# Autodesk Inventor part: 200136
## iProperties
Created: 2007-10
Part Number: 200136
Document SubType Name: Modeling
Designer: TH
Density: 7.85 g/cm^3
Mass: 540.598 g
Surface Area: 646.996 cm^2
Volume: 68.8659 cm^3
Material: Steel
Description: TOP BACK PLATE
Component Category: Lower Component
Author: TH
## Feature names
1. Extrusion1
2. Extrusion2
3. Mirror1
4. Extrusion3
5. Extrusion4
6. Extrusion5
7. Mirror2
8. Extrusion8
9. Extrusion9
10. Extrusion10
11. Mirror3
12. Fillet29
13. Fillet30
14. Fillet32
15. Fillet33
16. Fillet34
17. Fillet35
18. Fillet36
19. Fillet39
20. Fillet40
21. Fillet41
22. Extrusion11
23. Extrusion12
24. Fillet42
25. Fillet43
26. Fillet44
27. Fillet45
28. Mirror4
29. Fillet46
30. Fillet47
31. Fillet48
32. Hole1
33. Extrusion13
